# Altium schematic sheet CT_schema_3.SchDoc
size 316 x 185 mm
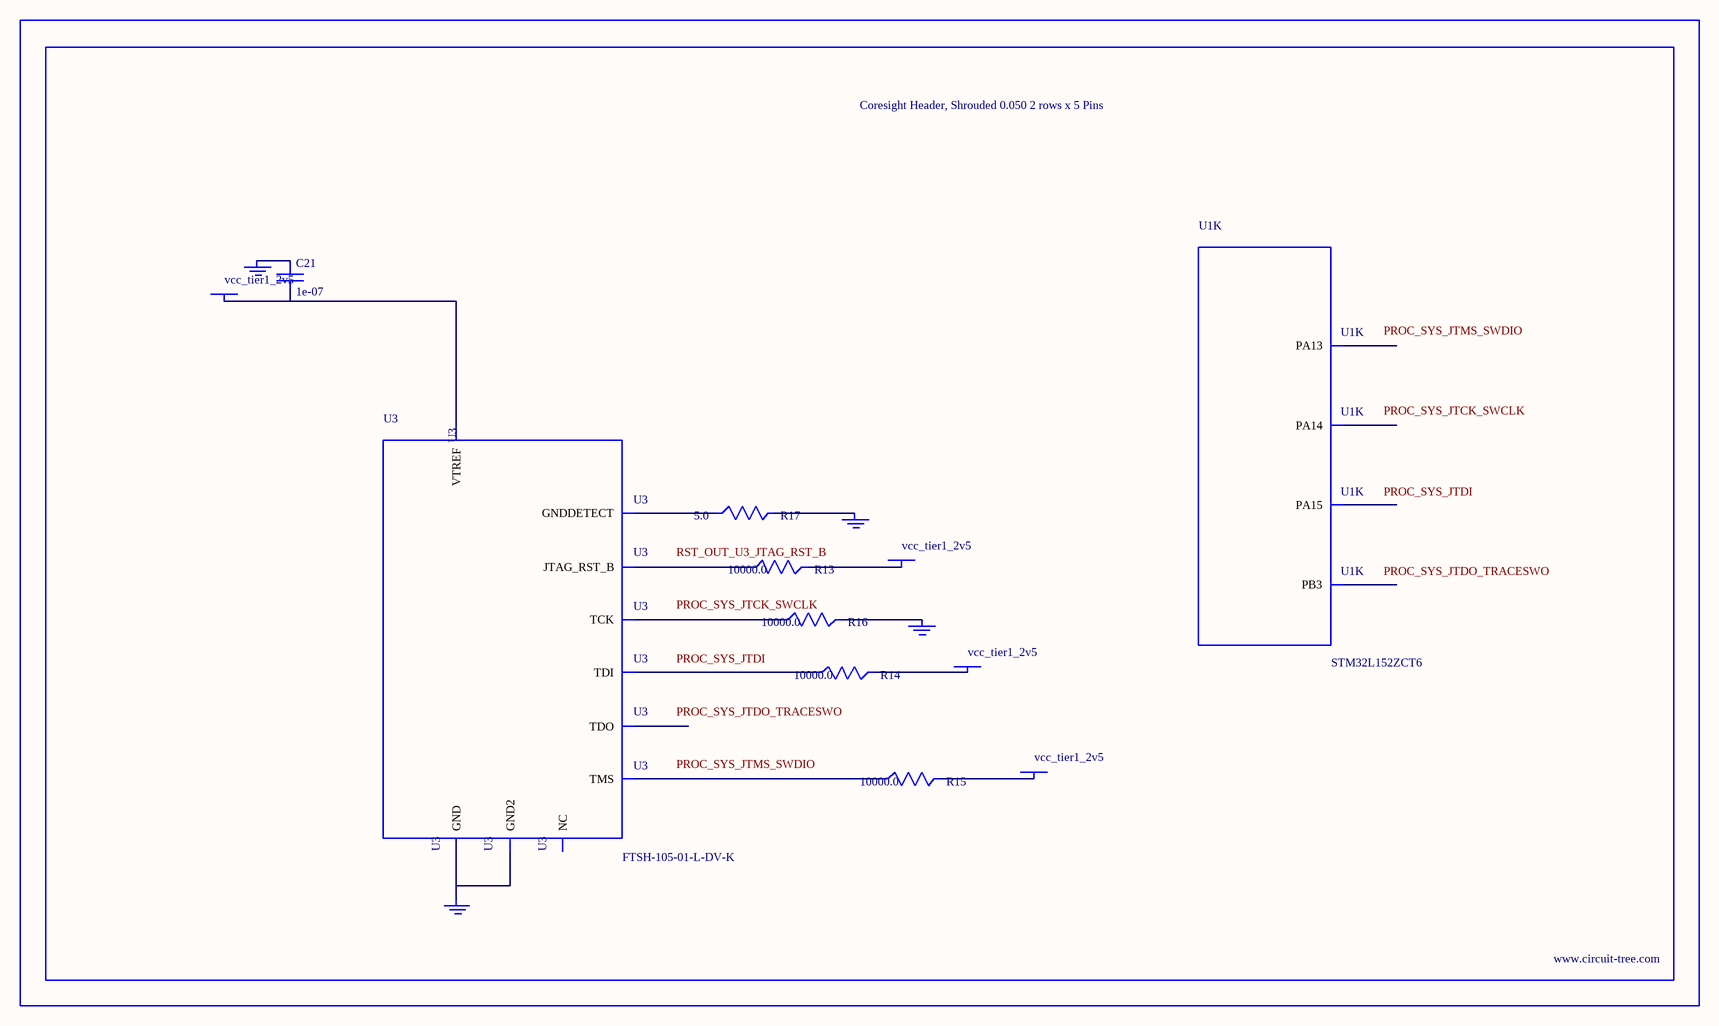
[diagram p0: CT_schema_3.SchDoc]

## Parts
BORDER2  (no value)
C21  1e-07  [C0402]
GND_INSTANCE_2_0  (no value)
GND_INSTANCE_2_1  (no value)
GND_INSTANCE_2_2  (no value)
GND_INSTANCE_2_3  (no value)
POWER_INSTANCE_2_0  vcc_tier1_2v5
POWER_INSTANCE_2_1  vcc_tier1_2v5
POWER_INSTANCE_2_2  vcc_tier1_2v5
POWER_INSTANCE_2_3  vcc_tier1_2v5
R13  10000.0  [R0603]
R14  10000.0  [R0603]
R15  10000.0  [R0603]
R16  10000.0  [R0603]
R17  5.0  [R0603]
U1  STM32L152ZCT6  [LQFP144]  (part K of 13)
U3  FTSH-105-01-L-DV-K  [SAMTEC_FTSH-105-01-L-DV-K]

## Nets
NetC21_1: C21.1 GND_INSTANCE_2_0.0(GND)
NetC21_2: C21.2 POWER_INSTANCE_2_0.0(PWR) U3.1(VTREF)
NetGND_INSTANCE_2_1_0: GND_INSTANCE_2_1.0(GND) R16.2
NetGND_INSTANCE_2_2_0: GND_INSTANCE_2_2.0(GND) R17.2
NetGND_INSTANCE_2_3_0: GND_INSTANCE_2_3.0(GND) U3.3(GND) U3.5(GND2)
NetPOWER_INSTANCE_2_1_0: POWER_INSTANCE_2_1.0(PWR) R15.2
NetPOWER_INSTANCE_2_2_0: POWER_INSTANCE_2_2.0(PWR) R14.2
NetPOWER_INSTANCE_2_3_0: POWER_INSTANCE_2_3.0(PWR) R13.2
NetR13_1: R13.1 U3.10(JTAG_RST_B)
NetR14_1: R14.1 U3.8(TDI)
NetR15_1: R15.1 U3.2(TMS)
NetR16_1: R16.1 U3.4(TCK)
NetR17_1: R17.1 U3.9(GNDDETECT)

Not connected (* = marked no-connect by the designer): U1 105(PA13) 109(PA14) 110(PA15) 133(PB3); U3 6(TDO) 7(NC)

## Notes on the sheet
- Labels drawn without touching a wire or pin: PROC_SYS_JTCK_SWCLK, PROC_SYS_JTDI, PROC_SYS_JTDO_TRACESWO, PROC_SYS_JTMS_SWDIO, RST_OUT_U3_JTAG_RST_B

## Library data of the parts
BORDER2 = BORDER_PAGE2
C21 = C0402C104K3RACTU
GND_INSTANCE_2_0-GND_INSTANCE_2_3 = GND
POWER_INSTANCE_2_0-POWER_INSTANCE_2_3 = PWR
R13-R16 = RC0603JR-0710KL
R17 = ERJ-3GEYJ5R1V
